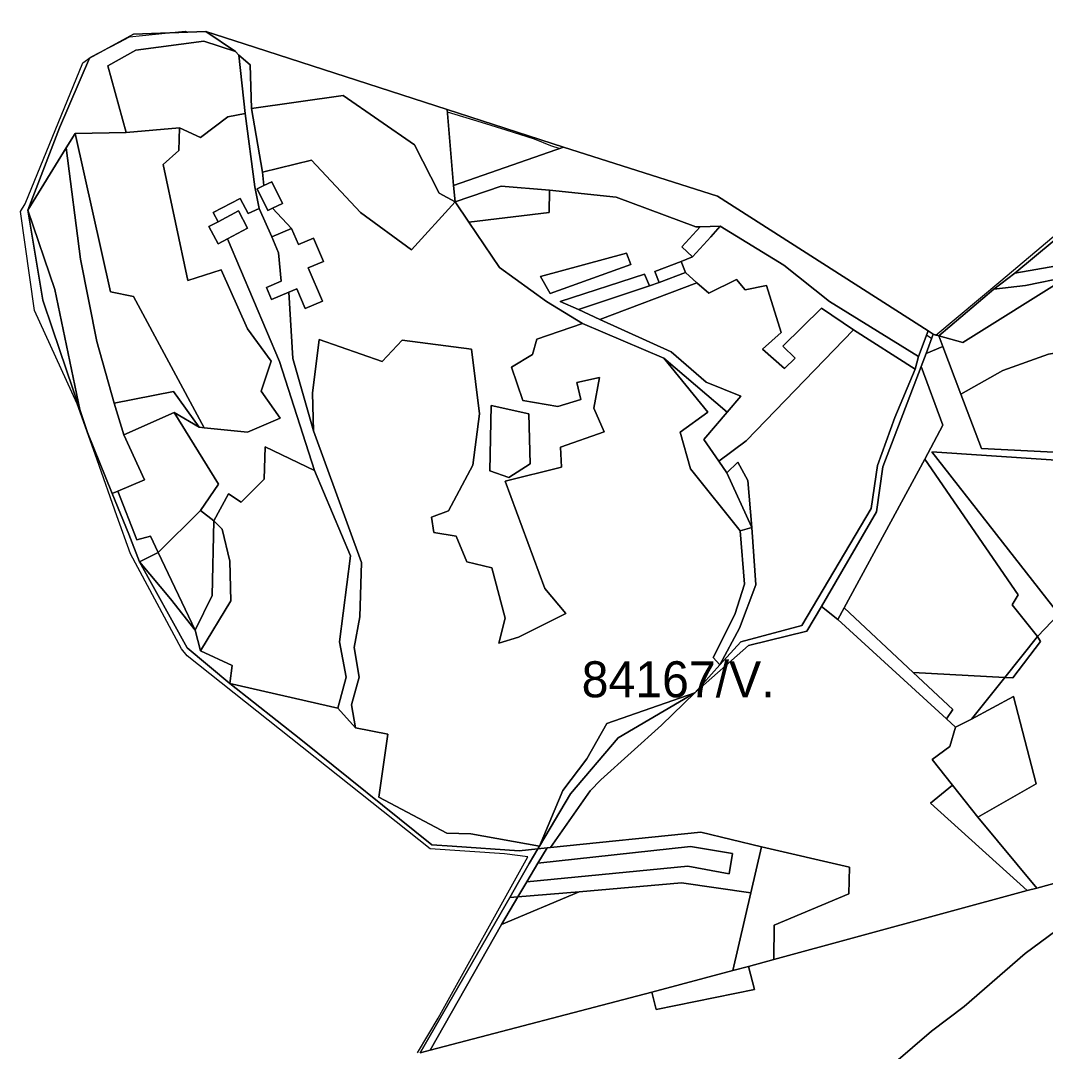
# Model space of a CAD drawing. Extents: x -477304 to -465429, y -1159113 to -1149210.
# Drawn here: x -472364 to -471937.5, y -1155113.8 to -1154684.7 of the extents above; entities that cross this region are included whole.
import ezdxf

# ---------------------------------------------------------------- set-up
doc = ezdxf.new("R2010")
doc.units = 0
for name, color, linetype in [('BPEJ_s', 7, 'Continuous'), ('orna_s', 7, 'Continuous'), ('ostatni_s', 7, 'Continuous'), ('PUPFL_s', 7, 'Continuous'), ('trav_porost_s', 7, 'Continuous')]:
    doc.layers.add(name, color=color, linetype=linetype)

msp = doc.modelspace()

# ---------------------------------------------------------------- linework, layer by layer
at = {"layer": 'BPEJ_s'}
for points in [[(-472338.06, -1154702.26), (-472334.66, -1154699.71), (-472322.89, -1154693.59), (-472318.72, -1154691.42), (-472302.39, -1154689.77), (-472295.56, -1154689.08), (-472294.38, -1154689.44), (-472286.96, -1154689.14), (-472270.9, -1154694.34), (-472186.49, -1154721.67), (-472186.41, -1154722.58), (-472172.32, -1154726.9), (-472161.98, -1154730.19), (-472150.23, -1154733.92), (-472143.42, -1154736.68), (-472139.59, -1154737.86), (-472137.97, -1154737.29), (-472073.9, -1154757.71), (-471986.31, -1154813.85), (-471986.94, -1154815.53), (-471984.75, -1154816.95), (-471984.11, -1154815.26), (-471983, -1154815.61), (-471956.02, -1154792.96), (-471932.09, -1154772.87)], [(-472318.72, -1154691.42), (-472302.39, -1154689.77), (-472295.56, -1154689.08), (-472294.38, -1154689.44), (-472286.96, -1154689.14), (-472270.9, -1154694.34), (-472186.49, -1154721.67), (-472186.41, -1154722.58), (-472172.32, -1154726.9), (-472161.98, -1154730.19), (-472150.23, -1154733.92), (-472143.42, -1154736.68), (-472139.59, -1154737.86), (-472137.97, -1154737.29), (-472073.9, -1154757.71), (-471986.31, -1154813.85), (-471986.94, -1154815.53), (-471984.75, -1154816.95), (-471984.11, -1154815.26), (-471983, -1154815.61), (-471956.02, -1154792.96), (-471932.09, -1154772.87)], [(-472198.79, -1155114.39), (-472190.17, -1155100.02), (-472152.85, -1155032.85), (-472162.55, -1155031.6), (-472193.57, -1155029.47), (-472294.71, -1154949.16), (-472297.05, -1154946.18), (-472318.3, -1154906.66), (-472323.9, -1154890.82), (-472332.12, -1154867.57), (-472340.39, -1154844.19), (-472358.24, -1154805.31), (-472363.98, -1154764.09), (-472362.07, -1154760.9), (-472338.06, -1154702.26), (-472334.66, -1154699.71), (-472322.89, -1154693.59), (-472318.72, -1154691.42)], [(-472198.79, -1155114.39), (-472190.17, -1155100.02), (-472152.85, -1155032.85), (-472162.55, -1155031.6), (-472193.57, -1155029.47), (-472294.71, -1154949.16), (-472297.05, -1154946.18), (-472318.3, -1154906.66), (-472323.9, -1154890.82), (-472332.12, -1154867.57), (-472340.39, -1154844.19), (-472358.24, -1154805.31), (-472363.98, -1154764.09), (-472362.07, -1154760.9), (-472338.06, -1154702.26)], [(-471933.07, -1155063.68), (-471945.82, -1155073.03), (-471971.32, -1155095.13), (-471984.92, -1155105.33), (-472000.64, -1155118.93)], [(-472000.64, -1155118.93), (-471984.92, -1155105.33), (-471971.32, -1155095.13), (-471945.82, -1155073.03), (-471933.07, -1155063.68)]]:
    msp.add_lwpolyline(points, dxfattribs=at)
at = {"layer": 'orna_s'}
for points in [[(-472259.72, -1154826.45), (-472263.85, -1154838.97), (-472256.02, -1154850.17), (-472269.53, -1154856.02), (-472287.61, -1154854.2), (-472317.05, -1154799.59), (-472326.54, -1154797.6), (-472341.31, -1154731.63), (-472320.03, -1154731.3), (-472297.87, -1154729.26), (-472298.14, -1154738.8), (-472304.59, -1154744.54), (-472294.34, -1154792.91), (-472280.5, -1154788.45), (-472269.53, -1154813.05)], [(-472076.68, -1154774.75), (-472072.76, -1154770.21), (-472046.3, -1154786.51), (-472027.3, -1154801.58), (-471990.31, -1154824.49), (-471991.62, -1154829.72), (-472017.36, -1154813.35), (-472030.63, -1154804.4), (-472046.68, -1154820.27), (-472041.66, -1154825.25), (-472046, -1154829.57), (-472055.14, -1154821.51), (-472047.44, -1154814.47), (-472053.51, -1154795.01), (-472062.38, -1154796.72), (-472066.07, -1154792.5), (-472077.51, -1154798.18), (-472082.51, -1154793.78), (-472087.3, -1154789.57), (-472089.06, -1154784.92), (-472084.35, -1154782.95)], [(-472289.68, -1154853.92), (-472300.13, -1154847.82), (-472320.97, -1154857.15), (-472325.08, -1154843.99), (-472300.29, -1154839.11)], [(-472315.65, -1154900.83), (-472323.56, -1154880.57), (-472312.45, -1154875.79), (-472320.97, -1154857.15), (-472300.13, -1154847.82), (-472281.66, -1154877.69), (-472289.16, -1154888.61), (-472306.8, -1154906.07), (-472309.94, -1154899.29)], [(-472289.13, -1154947), (-472291.28, -1154938.45), (-472284.22, -1154924.05), (-472283.51, -1154892.89), (-472280.03, -1154896.45), (-472276.86, -1154909.74), (-472276.42, -1154926.2)]]:
    msp.add_lwpolyline(points, close=True, dxfattribs=at)
at = {"layer": 'ostatni_s'}
for points in [[(-472264.73, -1154762.91), (-472266.55, -1154753.86), (-472270.52, -1154723.3), (-472273.22, -1154699.09), (-472268.45, -1154703.09), (-472267.82, -1154721.32), (-472263.35, -1154747.71), (-472262.76, -1154753.36), (-472265.49, -1154754.67), (-472261.12, -1154763.75), (-472259.1, -1154762.78), (-472251.19, -1154771.2), (-472259.48, -1154774.71)], [(-472265.49, -1154754.67), (-472262.76, -1154753.36), (-472259.41, -1154751.75), (-472255.03, -1154760.84), (-472259.1, -1154762.78), (-472261.12, -1154763.75)], [(-472226.22, -1154969.59), (-472224.54, -1154979.07), (-472231.98, -1154970.91), (-472228.51, -1154957.98), (-472231.21, -1154943.25), (-472226.75, -1154907.56), (-472241.69, -1154871.93), (-472256.19, -1154826.59), (-472277.92, -1154775.49), (-472269.56, -1154771.1), (-472273.34, -1154763.89), (-472281.8, -1154768.43), (-472283.85, -1154764.57), (-472272.6, -1154758.66), (-472269.22, -1154765.03), (-472264.73, -1154762.91), (-472259.48, -1154774.71), (-472256.66, -1154781.37), (-472255.6, -1154793.19), (-472261.61, -1154795.73), (-472259.5, -1154800.75), (-472252.38, -1154797.74), (-472250.65, -1154825.38), (-472242.02, -1154855.52), (-472222.09, -1154910.29), (-472222.8, -1154932.85), (-472225.17, -1154945.59), (-472223.13, -1154958)], [(-472273.34, -1154763.89), (-472269.56, -1154771.1), (-472277.92, -1154775.49), (-472281.82, -1154777.54), (-472285.58, -1154770.45), (-472281.8, -1154768.43)], [(-472244.24, -1154787.63), (-472238.39, -1154801.47), (-472245.51, -1154804.48), (-472248.97, -1154796.3), (-472252.38, -1154797.74), (-472259.5, -1154800.75), (-472261.61, -1154795.73), (-472255.6, -1154793.19), (-472256.66, -1154781.37), (-472259.48, -1154774.71), (-472251.19, -1154771.2), (-472248.37, -1154777.86), (-472242.07, -1154775.2), (-472237.94, -1154784.97)], [(-472084.35, -1154782.95), (-472088.8, -1154778.79), (-472081.13, -1154770.59), (-472072.76, -1154770.21), (-472076.68, -1154774.75)], [(-472089.06, -1154784.92), (-472087.3, -1154789.57), (-472098.2, -1154793.71), (-472099.96, -1154789.06)], [(-472036.69, -1154938.82), (-472061.05, -1154944.85), (-472083.36, -1154964.49), (-472073.02, -1154952.89), (-472064.18, -1154943.29), (-472038.86, -1154936.47), (-472010.03, -1154887.84), (-472007.35, -1154869.83), (-472000.16, -1154849.91), (-471991.62, -1154829.72), (-471990.31, -1154824.49), (-471986.31, -1154813.85), (-471984.11, -1154815.26), (-471987.12, -1154823.19), (-471989.2, -1154828.66), (-472005.06, -1154870.46), (-472007.7, -1154889.11), (-472030.71, -1154928.56)], [(-471987.58, -1154867.25), (-472021.26, -1154929.15), (-472023.89, -1154933.98), (-472030.71, -1154928.56), (-472007.7, -1154889.11), (-472005.06, -1154870.46), (-471989.2, -1154828.66), (-471980.14, -1154853.07)], [(-472152.48, -1154848.35), (-472151.93, -1154869.2), (-472160.81, -1154874.88), (-472168.64, -1154872.12), (-472168.08, -1154844.87)], [(-472057.97, -1154919.54), (-472064.76, -1154937.54), (-472073.02, -1154952.89), (-472075.74, -1154949.78), (-472066.71, -1154931.94), (-472062.68, -1154919.24), (-472064.51, -1154897.09), (-472059.62, -1154895.66)], [(-471978.66, -1154975.36), (-472023.89, -1154933.98), (-472021.26, -1154929.15), (-471992.43, -1154956.1), (-471976.03, -1154971.43)], [(-472135.06, -1155006.54), (-472115.31, -1154983.22), (-472083.36, -1154964.49), (-472097.22, -1154977.99), (-472122.46, -1155000.76), (-472126.93, -1155005.29), (-472143.47, -1155028.94), (-472144.85, -1155029.08), (-472148.71, -1155029.48), (-472148.08, -1155028.42)], [(-472144.85, -1155029.08), (-472143.47, -1155028.94), (-472080.88, -1155022.51), (-472055.58, -1155028.71), (-472060.01, -1155047.77), (-472088.93, -1155043.65), (-472131.52, -1155047.32), (-472156.98, -1155049.47), (-472153.23, -1155043.17), (-472086.27, -1155036.73), (-472069.06, -1155039.89), (-472067.75, -1155031.37), (-472085.17, -1155028.54), (-472148.65, -1155035.46)], [(-472152.27, -1155035.64), (-472148.71, -1155029.48), (-472144.85, -1155029.08), (-472148.65, -1155035.46), (-472153.23, -1155043.17), (-472156.98, -1155049.47), (-472160.42, -1155049.76), (-472156.72, -1155043.35)], [(-472067.54, -1155080.17), (-472060.01, -1155047.77), (-472055.58, -1155028.71), (-472019.04, -1155037.13), (-472019.22, -1155048.14), (-472050.31, -1155061.31), (-472050.5, -1155075.54), (-472061.07, -1155078.41)], [(-472193.51, -1155113.25), (-472197.72, -1155114.35), (-472160.42, -1155049.76), (-472156.98, -1155049.47), (-472163.79, -1155060.91)], [(-472163.79, -1155060.91), (-472156.98, -1155049.47), (-472131.52, -1155047.32)]]:
    msp.add_lwpolyline(points, close=True, dxfattribs=at)
at = {"layer": 'PUPFL_s'}
for points in [[(-471850.45, -1154768), (-471895.31, -1154780.25), (-471950.15, -1154789.78), (-471893.78, -1154742.87), (-471893.09, -1154686.85), (-471879.45, -1154684.67), (-471870.73, -1154712.25), (-471859.03, -1154750.35)], [(-472335.25, -1154700.33), (-472316.99, -1154690.37), (-472286.96, -1154689.14), (-472274.49, -1154697.55), (-472287.78, -1154693.24), (-472316.01, -1154696.99), (-472327.75, -1154703.56), (-472320.03, -1154731.3), (-472341.31, -1154731.63), (-472344.98, -1154737.6), (-472360.95, -1154763.64), (-472347.78, -1154729.26)], [(-472137.97, -1154737.29), (-472183.76, -1154753.29), (-472186.49, -1154721.67)], [(-472339.11, -1154783.95), (-472332.22, -1154818.2), (-472325.08, -1154843.99), (-472320.97, -1154857.15), (-472312.45, -1154875.79), (-472323.56, -1154880.57), (-472325.83, -1154881.54), (-472336.13, -1154856.09), (-472339.33, -1154846.63), (-472349.75, -1154796.55), (-472360.95, -1154763.64), (-472344.98, -1154737.6)], [(-472360.95, -1154763.64), (-472349.75, -1154796.55), (-472339.33, -1154846.63), (-472350.72, -1154812.94), (-472354.76, -1154800.99)], [(-471950.15, -1154789.78), (-471895.31, -1154780.25), (-471850.45, -1154768), (-471839.09, -1154774.06), (-471858.44, -1154778.38), (-471910, -1154788.3), (-471928.07, -1154791.39), (-471945.68, -1154794.92), (-471958.86, -1154796.48)], [(-471971.76, -1154818.68), (-471981.84, -1154815.97), (-471958.86, -1154796.48), (-471945.68, -1154794.92), (-471928.07, -1154791.39)], [(-471875.22, -1154887.6), (-471846.92, -1154882.29), (-471846.35, -1154874.44), (-471864.69, -1154872.31), (-471865.77, -1154867.9), (-471829.07, -1154870.85), (-471770.61, -1154873.07), (-471792.23, -1154942.61), (-471811.08, -1155010.04), (-471941.08, -1155045.78), (-471965.58, -1155016.24), (-471941.23, -1155002.36), (-471950.8, -1154966.12), (-471968.26, -1154975.44), (-471954.4, -1154958.13), (-471951.01, -1154958.31), (-471939.52, -1154943.16), (-471940.76, -1154941.09), (-471931.9, -1154931.83), (-471919.43, -1154946.61), (-471872.06, -1154930.71)], [(-471939.52, -1154943.16), (-471951.01, -1154958.31), (-471954.4, -1154958.13), (-471940.76, -1154941.09)], [(-472184.34, -1155028.41), (-472192.84, -1155027.83), (-472247.36, -1154983.94), (-472276.89, -1154960.68), (-472231.98, -1154970.91), (-472224.54, -1154979.07), (-472211.09, -1154981.72), (-472214.87, -1155008.03), (-472186.58, -1155022.92), (-472176.66, -1155023.26), (-472148.08, -1155028.42), (-472148.71, -1155029.48), (-472156.43, -1155030.32)], [(-471968.26, -1154975.44), (-471950.8, -1154966.12), (-471941.23, -1155002.36), (-471965.58, -1155016.24), (-471976.09, -1155002.99), (-471984.58, -1154992.28), (-471977.27, -1154986.83), (-471974.91, -1154978.79)], [(-471976.09, -1155002.99), (-471965.58, -1155016.24), (-471941.08, -1155045.78), (-471945.03, -1155046.85), (-471985.26, -1155010.53)], [(-472058.6, -1155088.1), (-472099.41, -1155096.37), (-472101.22, -1155089.12), (-472067.54, -1155080.17), (-472061.07, -1155078.41)]]:
    msp.add_lwpolyline(points, close=True, dxfattribs=at)
for points in [[(-471893.78, -1154742.87), (-471950.15, -1154789.78), (-471958.86, -1154796.48), (-471981.84, -1154815.97), (-471984.11, -1154815.26), (-471986.31, -1154813.85), (-472073.9, -1154757.71), (-472137.97, -1154737.29), (-472186.49, -1154721.67), (-472270.9, -1154694.34), (-472286.96, -1154689.14), (-472316.99, -1154690.37), (-472335.25, -1154700.33), (-472347.78, -1154729.26), (-472360.95, -1154763.64), (-472354.76, -1154800.99), (-472350.72, -1154812.94), (-472339.33, -1154846.63), (-472336.13, -1154856.09), (-472325.83, -1154881.54), (-472318.98, -1154898.47), (-472314.44, -1154909.93), (-472294.71, -1154945.82), (-472276.89, -1154960.68), (-472247.36, -1154983.94), (-472192.84, -1155027.83), (-472184.34, -1155028.41), (-472156.43, -1155030.32), (-472148.71, -1155029.48), (-472152.27, -1155035.64), (-472156.72, -1155043.35), (-472160.42, -1155049.76), (-472197.72, -1155114.35)], [(-472197.72, -1155114.35), (-472193.51, -1155113.25), (-472101.22, -1155089.12), (-472099.41, -1155096.37), (-472058.6, -1155088.1), (-472061.07, -1155078.41), (-472050.5, -1155075.54), (-471945.03, -1155046.85), (-471941.08, -1155045.78), (-471811.08, -1155010.04)]]:
    msp.add_lwpolyline(points, dxfattribs=at)
at = {"layer": 'trav_porost_s'}
for points in [[(-472267.82, -1154721.32), (-472268.45, -1154703.09), (-472273.22, -1154699.09), (-472274.49, -1154697.55), (-472286.96, -1154689.14), (-472270.9, -1154694.34), (-472186.49, -1154721.67), (-472183.76, -1154753.29), (-472183.17, -1154760.06), (-472189.81, -1154756.54), (-472200.06, -1154736.32), (-472229.78, -1154715.86)], [(-472297.87, -1154729.26), (-472320.03, -1154731.3), (-472327.75, -1154703.56), (-472316.01, -1154696.99), (-472287.78, -1154693.24), (-472274.49, -1154697.55), (-472273.22, -1154699.09), (-472270.52, -1154723.3), (-472277.69, -1154724.79), (-472289.05, -1154733.4)], [(-472263.35, -1154747.71), (-472267.82, -1154721.32), (-472229.78, -1154715.86), (-472200.06, -1154736.32), (-472189.81, -1154756.54), (-472183.17, -1154760.06), (-472201.33, -1154780.09), (-472222.5, -1154764.54), (-472242.9, -1154742.75)], [(-472281.66, -1154877.69), (-472300.13, -1154847.82), (-472289.68, -1154853.92), (-472287.61, -1154854.2), (-472269.53, -1154856.02), (-472256.02, -1154850.17), (-472263.85, -1154838.97), (-472259.72, -1154826.45), (-472269.53, -1154813.05), (-472280.5, -1154788.45), (-472294.34, -1154792.91), (-472304.59, -1154744.54), (-472298.14, -1154738.8), (-472297.87, -1154729.26), (-472289.05, -1154733.4), (-472277.69, -1154724.79), (-472270.52, -1154723.3), (-472266.55, -1154753.86), (-472264.73, -1154762.91), (-472269.22, -1154765.03), (-472272.6, -1154758.66), (-472283.85, -1154764.57), (-472281.8, -1154768.43), (-472285.58, -1154770.45), (-472281.82, -1154777.54), (-472277.92, -1154775.49), (-472256.19, -1154826.59), (-472241.69, -1154871.93), (-472262.14, -1154862.11), (-472262.61, -1154875.51), (-472272.2, -1154885.19), (-472277.5, -1154881.69), (-472283.51, -1154892.89), (-472289.16, -1154888.61)], [(-472325.08, -1154843.99), (-472332.22, -1154818.2), (-472339.11, -1154783.95), (-472344.98, -1154737.6), (-472341.31, -1154731.63), (-472326.54, -1154797.6), (-472317.05, -1154799.59), (-472287.61, -1154854.2), (-472289.68, -1154853.92), (-472300.29, -1154839.11)], [(-472137.97, -1154737.29), (-472073.9, -1154757.71), (-471986.31, -1154813.85), (-471990.31, -1154824.49), (-472027.3, -1154801.58), (-472046.3, -1154786.51), (-472072.76, -1154770.21), (-472081.13, -1154770.59), (-472082.94, -1154770.55), (-472116.17, -1154758.21), (-472143.89, -1154755.3), (-472163.92, -1154753.57), (-472183.17, -1154760.06), (-472183.76, -1154753.29)], [(-472245.51, -1154804.48), (-472238.39, -1154801.47), (-472244.24, -1154787.63), (-472237.94, -1154784.97), (-472242.07, -1154775.2), (-472248.37, -1154777.86), (-472251.19, -1154771.2), (-472259.1, -1154762.78), (-472255.03, -1154760.84), (-472259.41, -1154751.75), (-472262.76, -1154753.36), (-472263.35, -1154747.71), (-472242.9, -1154742.75), (-472222.5, -1154764.54), (-472201.33, -1154780.09), (-472183.17, -1154760.06), (-472177.41, -1154768.55), (-472164.62, -1154787.4), (-472145.1, -1154801.66), (-472130.1, -1154810.78), (-472149.06, -1154817.35), (-472150.94, -1154823.64), (-472159.65, -1154828.88), (-472154.96, -1154842.83), (-472140.41, -1154845.37), (-472130.87, -1154842.45), (-472132.47, -1154835.33), (-472122.99, -1154833.24), (-472125.36, -1154845.98), (-472121.06, -1154855.85), (-472139.25, -1154862.19), (-472138.86, -1154870.58), (-472162.35, -1154876.37), (-472145.76, -1154921.1), (-472137.04, -1154931.53), (-472156.78, -1154941.35), (-472164.89, -1154943.83), (-472162.3, -1154933.51), (-472167.86, -1154912.55), (-472178.28, -1154909.96), (-472182.64, -1154899.37), (-472191.96, -1154897.72), (-472192.95, -1154891.37), (-472185.95, -1154888.78), (-472175.75, -1154869.69), (-472172.94, -1154848.35), (-472176.35, -1154821.49), (-472205.19, -1154817.68), (-472213.46, -1154826.56), (-472239.7, -1154817.4), (-472242.46, -1154839.74), (-472242.02, -1154855.52), (-472250.65, -1154825.38), (-472252.38, -1154797.74), (-472248.97, -1154796.3)], [(-472183.17, -1154760.06), (-472163.92, -1154753.57), (-472143.89, -1154755.3), (-472143.97, -1154764.62), (-472177.41, -1154768.55)], [(-472081.13, -1154770.59), (-472088.8, -1154778.79), (-472084.35, -1154782.95), (-472089.06, -1154784.92), (-472099.96, -1154789.06), (-472098.2, -1154793.71), (-472102.27, -1154795.08), (-472104.31, -1154790.18), (-472139.36, -1154801.58), (-472131.77, -1154804.99), (-472122.87, -1154809.04), (-472093.25, -1154822.5), (-472078.68, -1154835.21), (-472064.17, -1154841.07), (-472069.97, -1154847.64), (-472096.3, -1154825.24), (-472130.1, -1154810.78), (-472145.1, -1154801.66), (-472164.62, -1154787.4), (-472177.41, -1154768.55), (-472143.97, -1154764.62), (-472143.89, -1154755.3), (-472116.17, -1154758.21), (-472082.94, -1154770.55)], [(-472143.55, -1154798.26), (-472109.96, -1154786.2), (-472111.82, -1154781.55), (-472147.66, -1154791.24)], [(-472109.96, -1154786.2), (-472143.55, -1154798.26), (-472147.66, -1154791.24), (-472111.82, -1154781.55)], [(-471923.74, -1154821.43), (-471936.23, -1154823.6), (-471955.21, -1154830.39), (-471972.71, -1154840.25), (-471980.19, -1154820.35), (-471981.84, -1154815.97), (-471971.76, -1154818.68), (-471928.07, -1154791.39), (-471910, -1154788.3), (-471893.54, -1154820.87)], [(-472139.36, -1154801.58), (-472104.31, -1154790.18), (-472102.27, -1154795.08), (-472131.77, -1154804.99)], [(-472131.77, -1154804.99), (-472102.27, -1154795.08), (-472098.2, -1154793.71), (-472087.3, -1154789.57), (-472082.51, -1154793.78), (-472122.87, -1154809.04)], [(-472046.68, -1154820.27), (-472030.63, -1154804.4), (-472017.36, -1154813.35), (-472061.97, -1154859.62), (-472073.37, -1154868.08), (-472079.62, -1154859.12), (-472069.97, -1154847.64), (-472064.17, -1154841.07), (-472078.68, -1154835.21), (-472093.25, -1154822.5), (-472122.87, -1154809.04), (-472082.51, -1154793.78), (-472077.51, -1154798.18), (-472066.07, -1154792.5), (-472062.38, -1154796.72), (-472053.51, -1154795.01), (-472047.44, -1154814.47), (-472055.14, -1154821.51), (-472046, -1154829.57), (-472041.66, -1154825.25)], [(-472064.51, -1154897.09), (-472062.68, -1154919.24), (-472066.71, -1154931.94), (-472075.74, -1154949.78), (-472073.02, -1154952.89), (-472083.36, -1154964.49), (-472119.93, -1154977.25), (-472128.36, -1154992.04), (-472138.34, -1155005.22), (-472148.08, -1155028.42), (-472176.66, -1155023.26), (-472186.58, -1155022.92), (-472214.87, -1155008.03), (-472211.09, -1154981.72), (-472224.54, -1154979.07), (-472226.22, -1154969.59), (-472223.13, -1154958), (-472225.17, -1154945.59), (-472222.8, -1154932.85), (-472222.09, -1154910.29), (-472242.02, -1154855.52), (-472242.46, -1154839.74), (-472239.7, -1154817.4), (-472213.46, -1154826.56), (-472205.19, -1154817.68), (-472176.35, -1154821.49), (-472172.94, -1154848.35), (-472175.75, -1154869.69), (-472185.95, -1154888.78), (-472192.95, -1154891.37), (-472191.96, -1154897.72), (-472182.64, -1154899.37), (-472178.28, -1154909.96), (-472167.86, -1154912.55), (-472162.3, -1154933.51), (-472164.89, -1154943.83), (-472156.78, -1154941.35), (-472137.04, -1154931.53), (-472145.76, -1154921.1), (-472162.35, -1154876.37), (-472138.86, -1154870.58), (-472139.25, -1154862.19), (-472121.06, -1154855.85), (-472125.36, -1154845.98), (-472122.99, -1154833.24), (-472132.47, -1154835.33), (-472130.87, -1154842.45), (-472140.41, -1154845.37), (-472154.96, -1154842.83), (-472159.65, -1154828.88), (-472150.94, -1154823.64), (-472149.06, -1154817.35), (-472130.1, -1154810.78), (-472096.3, -1154825.24), (-472078, -1154847.64), (-472089.51, -1154856.07), (-472085.13, -1154871.28)], [(-472061.33, -1154876.08), (-472065.43, -1154868.44), (-472069.99, -1154872.91), (-472073.37, -1154868.08), (-472061.97, -1154859.62), (-472017.36, -1154813.35), (-471991.62, -1154829.72), (-472000.16, -1154849.91), (-472007.35, -1154869.83), (-472010.03, -1154887.84), (-472038.86, -1154936.47), (-472064.18, -1154943.29), (-472073.02, -1154952.89), (-472064.76, -1154937.54), (-472057.97, -1154919.54), (-472059.62, -1154895.66)], [(-471984.11, -1154815.26), (-471981.84, -1154815.97), (-471980.19, -1154820.35), (-471987.12, -1154823.19)], [(-471951.28, -1154927.84), (-471948.8, -1154923.75), (-471987.58, -1154867.25), (-471980.14, -1154853.07), (-471989.2, -1154828.66), (-471987.12, -1154823.19), (-471980.19, -1154820.35), (-471972.71, -1154840.25), (-471964, -1154862.77), (-471868.32, -1154867.7), (-471865.77, -1154867.9), (-471864.69, -1154872.31), (-471984.79, -1154864.2), (-471931.9, -1154931.83), (-471940.76, -1154941.09)], [(-471964, -1154862.77), (-471972.71, -1154840.25), (-471955.21, -1154830.39), (-471936.23, -1154823.6), (-471923.74, -1154821.43), (-471893.54, -1154820.87), (-471890.08, -1154820.98), (-471878.51, -1154848.39), (-471868.32, -1154867.7)], [(-472069.97, -1154847.64), (-472079.62, -1154859.12), (-472073.37, -1154868.08), (-472069.99, -1154872.91), (-472059.62, -1154895.66), (-472064.51, -1154897.09), (-472085.13, -1154871.28), (-472089.51, -1154856.07), (-472078, -1154847.64), (-472096.3, -1154825.24)], [(-472168.64, -1154872.12), (-472160.81, -1154874.88), (-472151.93, -1154869.2), (-472152.48, -1154848.35), (-472168.08, -1154844.87)], [(-472277.5, -1154881.69), (-472272.2, -1154885.19), (-472262.61, -1154875.51), (-472262.14, -1154862.11), (-472241.69, -1154871.93), (-472226.75, -1154907.56), (-472231.21, -1154943.25), (-472228.51, -1154957.98), (-472231.98, -1154970.91), (-472276.89, -1154960.68), (-472275.87, -1154953.2), (-472289.13, -1154947), (-472276.42, -1154926.2), (-472276.86, -1154909.74), (-472280.03, -1154896.45), (-472283.51, -1154892.89)], [(-471864.69, -1154872.31), (-471931.9, -1154931.83), (-471984.79, -1154864.2)], [(-472069.99, -1154872.91), (-472065.43, -1154868.44), (-472061.33, -1154876.08), (-472059.62, -1154895.66)], [(-471951.28, -1154927.84), (-471940.76, -1154941.09), (-471954.4, -1154958.13), (-471992.43, -1154956.1), (-472021.26, -1154929.15), (-471987.58, -1154867.25), (-471948.8, -1154923.75)], [(-472325.83, -1154881.54), (-472323.56, -1154880.57), (-472315.65, -1154900.83), (-472309.94, -1154899.29), (-472306.8, -1154906.07), (-472314.44, -1154909.93), (-472318.98, -1154898.47)], [(-472289.16, -1154888.61), (-472283.51, -1154892.89), (-472284.22, -1154924.05), (-472291.28, -1154938.45), (-472306.8, -1154906.07)], [(-472301.64, -1154925.43), (-472314.44, -1154909.93), (-472306.8, -1154906.07), (-472291.28, -1154938.45)], [(-472314.44, -1154909.93), (-472301.64, -1154925.43), (-472291.28, -1154938.45), (-472289.13, -1154947), (-472275.87, -1154953.2), (-472276.89, -1154960.68), (-472294.71, -1154945.82)], [(-472050.5, -1155075.54), (-472050.31, -1155061.31), (-472019.22, -1155048.14), (-472019.04, -1155037.13), (-472055.58, -1155028.71), (-472080.88, -1155022.51), (-472143.47, -1155028.94), (-472126.93, -1155005.29), (-472122.46, -1155000.76), (-472097.22, -1154977.99), (-472083.36, -1154964.49), (-472061.05, -1154944.85), (-472036.69, -1154938.82), (-472030.71, -1154928.56), (-472023.89, -1154933.98), (-471978.66, -1154975.36), (-471974.91, -1154978.79), (-471977.27, -1154986.83), (-471984.58, -1154992.28), (-471976.09, -1155002.99), (-471985.26, -1155010.53), (-471945.03, -1155046.85)], [(-471968.26, -1154975.44), (-471974.91, -1154978.79), (-471978.66, -1154975.36), (-471976.03, -1154971.43), (-471992.43, -1154956.1), (-471954.4, -1154958.13)], [(-472119.93, -1154977.25), (-472083.36, -1154964.49), (-472115.31, -1154983.22), (-472135.06, -1155006.54), (-472148.08, -1155028.42), (-472138.34, -1155005.22), (-472128.36, -1154992.04)], [(-472067.75, -1155031.37), (-472069.06, -1155039.89), (-472086.27, -1155036.73), (-472153.23, -1155043.17), (-472148.65, -1155035.46), (-472085.17, -1155028.54)], [(-472060.01, -1155047.77), (-472067.54, -1155080.17), (-472101.22, -1155089.12), (-472193.51, -1155113.25), (-472163.79, -1155060.91), (-472131.52, -1155047.32), (-472088.93, -1155043.65)]]:
    msp.add_lwpolyline(points, close=True, dxfattribs=at)

# ---------------------------------------------------------------- texts
at = {"layer": 'BPEJ_s'}
msp.add_text('84167/V.', height=15, dxfattribs=at).set_placement((-472130.47, -1154966.39))

doc.saveas('drawing.dxf')
